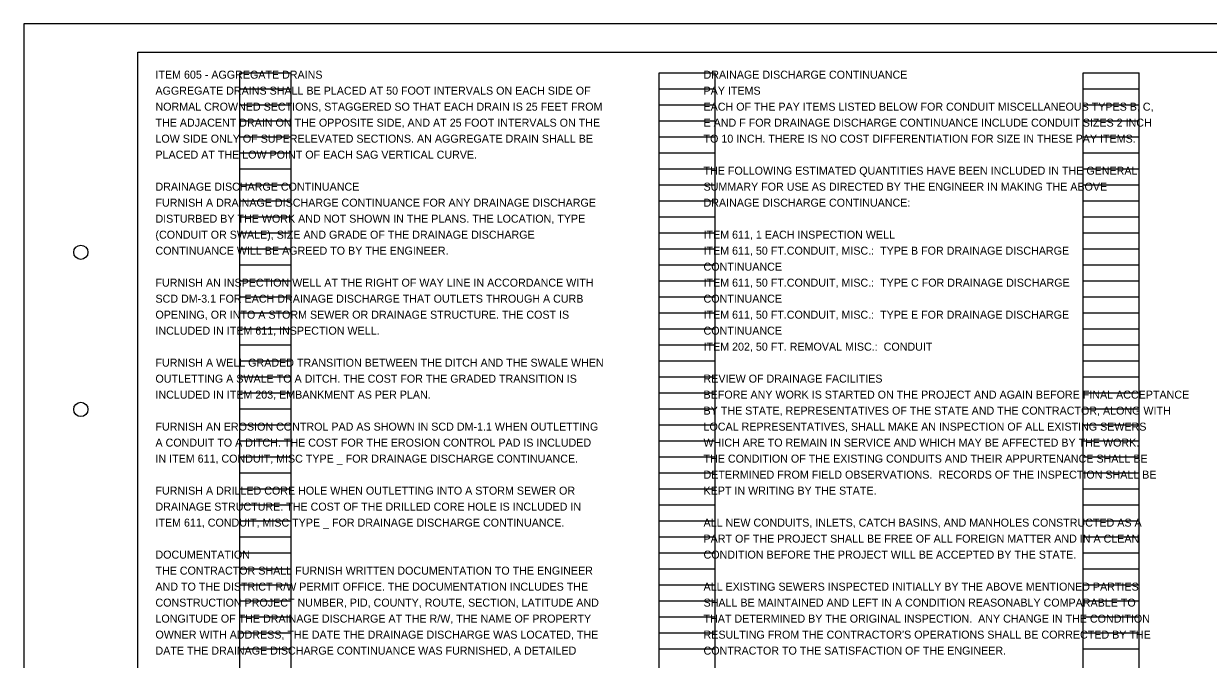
# Model space of a CAD drawing. Extents: x -16 to 102, y -13 to 9.
# Drawn here: x 27.86 to 48.59, y -2.03 to 9.09 of the extents above; entities that cross this region are included whole.
import ezdxf

# ---------------------------------------------------------------- set-up
doc = ezdxf.new("R2010")
doc.units = 0
for name, color, linetype in [('SH_Border', 7, 'Continuous'), ('SH_Cut_Line', 7, 'Continuous'), ('SH_Data', 7, 'Continuous'), ('TX_P_1', 7, 'Continuous')]:
    doc.layers.add(name, color=color, linetype=linetype)

msp = doc.modelspace()

# ---------------------------------------------------------------- linework, layer by layer
at = {"layer": 'SH_Border'}
msp.add_lwpolyline([(29.861, 8.593), (61.361, 8.593), (61.361, -12.407), (29.861, -12.407)], close=True, dxfattribs=at)
for centre in [(28.861, 5.093), (28.861, 2.343)]:
    msp.add_circle(centre, 0.125, dxfattribs=at)
at = {"layer": 'SH_Cut_Line'}
msp.add_lwpolyline([(27.861, -12.907), (61.861, -12.907), (61.861, 9.093), (27.861, 9.093)], close=True, dxfattribs=at)
at = {"layer": 'SH_Data'}
for p, q in [((31.642, -11.927), (31.642, 8.233)), ((31.642, 8.233), (32.542, 8.233)), ((32.542, -11.927), (32.542, 8.233)), ((38.982, -11.927), (38.982, 8.233)), ((38.982, 8.233), (39.962, 8.233)), ((39.962, -11.927), (39.962, 8.233)), ((46.402, -11.927), (46.402, 8.233)), ((46.402, 8.233), (47.382, 8.233)), ((47.382, -11.927), (47.382, 8.233)), ((31.642, 7.953), (32.542, 7.953)), ((38.982, 7.953), (39.962, 7.953)), ((46.402, 7.953), (47.382, 7.953)), ((31.642, 7.673), (32.542, 7.673)), ((38.982, 7.673), (39.962, 7.673)), ((46.402, 7.673), (47.382, 7.673)), ((31.642, 7.393), (32.542, 7.393)), ((38.982, 7.393), (39.962, 7.393)), ((46.402, 7.393), (47.382, 7.393)), ((31.642, 7.113), (32.542, 7.113)), ((38.982, 7.113), (39.962, 7.113)), ((46.402, 7.113), (47.382, 7.113)), ((31.642, 6.833), (32.542, 6.833)), ((38.982, 6.833), (39.962, 6.833)), ((46.402, 6.833), (47.382, 6.833)), ((31.642, 6.553), (32.542, 6.553)), ((38.982, 6.553), (39.962, 6.553)), ((46.402, 6.553), (47.382, 6.553)), ((31.642, 6.273), (32.542, 6.273)), ((38.982, 6.273), (39.962, 6.273)), ((46.402, 6.273), (47.382, 6.273)), ((31.642, 5.993), (32.542, 5.993)), ((38.982, 5.993), (39.962, 5.993)), ((46.402, 5.993), (47.382, 5.993)), ((31.642, 5.713), (32.542, 5.713)), ((38.982, 5.713), (39.962, 5.713)), ((46.402, 5.713), (47.382, 5.713)), ((31.642, 5.433), (32.542, 5.433)), ((38.982, 5.433), (39.962, 5.433)), ((46.402, 5.433), (47.382, 5.433)), ((31.642, 5.153), (32.542, 5.153)), ((38.982, 5.153), (39.962, 5.153)), ((46.402, 5.153), (47.382, 5.153)), ((31.642, 4.873), (32.542, 4.873)), ((38.982, 4.873), (39.962, 4.873)), ((46.402, 4.873), (47.382, 4.873)), ((31.642, 4.593), (32.542, 4.593)), ((38.982, 4.593), (39.962, 4.593)), ((46.402, 4.593), (47.382, 4.593)), ((31.642, 4.313), (32.542, 4.313)), ((38.982, 4.313), (39.962, 4.313)), ((46.402, 4.313), (47.382, 4.313)), ((31.642, 4.033), (32.542, 4.033)), ((38.982, 4.033), (39.962, 4.033)), ((46.402, 4.033), (47.382, 4.033)), ((31.642, 3.753), (32.542, 3.753)), ((38.982, 3.753), (39.962, 3.753)), ((46.402, 3.753), (47.382, 3.753)), ((31.642, 3.473), (32.542, 3.473)), ((38.982, 3.473), (39.962, 3.473)), ((46.402, 3.473), (47.382, 3.473)), ((31.642, 3.193), (32.542, 3.193)), ((38.982, 3.193), (39.962, 3.193)), ((46.402, 3.193), (47.382, 3.193)), ((31.642, 2.913), (32.542, 2.913)), ((38.982, 2.913), (39.962, 2.913)), ((46.402, 2.913), (47.382, 2.913)), ((31.642, 2.633), (32.542, 2.633)), ((38.982, 2.633), (39.962, 2.633)), ((46.402, 2.633), (47.382, 2.633)), ((31.642, 2.353), (32.542, 2.353)), ((38.982, 2.353), (39.962, 2.353)), ((46.402, 2.353), (47.382, 2.353)), ((31.642, 2.073), (32.542, 2.073)), ((38.982, 2.073), (39.962, 2.073)), ((46.402, 2.073), (47.382, 2.073)), ((31.642, 1.793), (32.542, 1.793)), ((38.982, 1.793), (39.962, 1.793)), ((46.402, 1.793), (47.382, 1.793)), ((31.642, 1.513), (32.542, 1.513)), ((38.982, 1.513), (39.962, 1.513)), ((46.402, 1.513), (47.382, 1.513)), ((31.642, 1.233), (32.542, 1.233)), ((38.982, 1.233), (39.962, 1.233)), ((46.402, 1.233), (47.382, 1.233)), ((31.642, 0.953), (32.542, 0.953)), ((38.982, 0.953), (39.962, 0.953)), ((46.402, 0.953), (47.382, 0.953)), ((31.642, 0.673), (32.542, 0.673)), ((38.982, 0.673), (39.962, 0.673)), ((46.402, 0.673), (47.382, 0.673)), ((31.642, 0.393), (32.542, 0.393)), ((38.982, 0.393), (39.962, 0.393)), ((46.402, 0.393), (47.382, 0.393)), ((31.642, 0.113), (32.542, 0.113)), ((38.982, 0.113), (39.962, 0.113)), ((46.402, 0.113), (47.382, 0.113)), ((31.642, -0.167), (32.542, -0.167)), ((38.982, -0.167), (39.962, -0.167)), ((46.402, -0.167), (47.382, -0.167)), ((31.642, -0.447), (32.542, -0.447)), ((38.982, -0.447), (39.962, -0.447)), ((46.402, -0.447), (47.382, -0.447)), ((31.642, -0.727), (32.542, -0.727)), ((38.982, -0.727), (39.962, -0.727)), ((46.402, -0.727), (47.382, -0.727)), ((31.642, -1.007), (32.542, -1.007)), ((38.982, -1.007), (39.962, -1.007)), ((46.402, -1.007), (47.382, -1.007)), ((31.642, -1.287), (32.542, -1.287)), ((38.982, -1.287), (39.962, -1.287)), ((46.402, -1.287), (47.382, -1.287)), ((31.642, -1.567), (32.542, -1.567)), ((38.982, -1.567), (39.962, -1.567)), ((46.402, -1.567), (47.382, -1.567)), ((31.642, -1.847), (32.542, -1.847)), ((38.982, -1.847), (39.962, -1.847)), ((46.402, -1.847), (47.382, -1.847))]:
    msp.add_line(p, q, dxfattribs=at)

# ---------------------------------------------------------------- texts
at = {"layer": 'TX_P_1'}
for s, p in [('ITEM 605 - AGGREGATE DRAINS', (30.167, 8.131)), ('DRAINAGE DISCHARGE CONTINUANCE', (39.758, 8.131)), ('AGGREGATE DRAINS SHALL BE PLACED AT 50 FOOT INTERVALS ON EACH SIDE OF', (30.167, 7.851)), ('PAY ITEMS', (39.758, 7.851)), ('NORMAL CROWNED SECTIONS, STAGGERED SO THAT EACH DRAIN IS 25 FEET FROM', (30.167, 7.571)), ('EACH OF THE PAY ITEMS LISTED BELOW FOR CONDUIT MISCELLANEOUS TYPES B, C,', (39.758, 7.571)), ('THE ADJACENT DRAIN ON THE OPPOSITE SIDE, AND AT 25 FOOT INTERVALS ON THE', (30.167, 7.291)), ('E AND F FOR DRAINAGE DISCHARGE CONTINUANCE INCLUDE CONDUIT SIZES 2 INCH', (39.758, 7.291)), ('LOW SIDE ONLY OF SUPERELEVATED SECTIONS. AN AGGREGATE DRAIN SHALL BE', (30.167, 7.011)), ('TO 10 INCH. THERE IS NO COST DIFFERENTIATION FOR SIZE IN THESE PAY ITEMS.', (39.758, 7.011)), ('PLACED AT THE LOW POINT OF EACH SAG VERTICAL CURVE.', (30.167, 6.731)), ('THE FOLLOWING ESTIMATED QUANTITIES HAVE BEEN INCLUDED IN THE GENERAL', (39.758, 6.451)), ('DRAINAGE DISCHARGE CONTINUANCE', (30.167, 6.171)), ('SUMMARY FOR USE AS DIRECTED BY THE ENGINEER IN MAKING THE ABOVE', (39.758, 6.171)), ('FURNISH A DRAINAGE DISCHARGE CONTINUANCE FOR ANY DRAINAGE DISCHARGE', (30.167, 5.891)), ('DRAINAGE DISCHARGE CONTINUANCE:', (39.758, 5.891)), ('DISTURBED BY THE WORK AND NOT SHOWN IN THE PLANS. THE LOCATION, TYPE', (30.167, 5.611)), ('(CONDUIT OR SWALE), SIZE AND GRADE OF THE DRAINAGE DISCHARGE', (30.167, 5.331)), ('ITEM 611, 1 EACH INSPECTION WELL', (39.758, 5.331)), ('CONTINUANCE WILL BE AGREED TO BY THE ENGINEER.', (30.167, 5.051)), ('ITEM 611, 50 FT.CONDUIT, MISC.:  TYPE B FOR DRAINAGE DISCHARGE', (39.758, 5.051)), ('CONTINUANCE ', (39.758, 4.771)), ('FURNISH AN INSPECTION WELL AT THE RIGHT OF WAY LINE IN ACCORDANCE WITH', (30.167, 4.491)), ('ITEM 611, 50 FT.CONDUIT, MISC.:  TYPE C FOR DRAINAGE DISCHARGE', (39.758, 4.491)), ('SCD DM-3.1 FOR EACH DRAINAGE DISCHARGE THAT OUTLETS THROUGH A CURB', (30.167, 4.211)), ('CONTINUANCE', (39.758, 4.211)), ('OPENING, OR INTO A STORM SEWER OR DRAINAGE STRUCTURE. THE COST IS', (30.167, 3.931)), ('ITEM 611, 50 FT.CONDUIT, MISC.:  TYPE E FOR DRAINAGE DISCHARGE', (39.758, 3.931)), ('INCLUDED IN ITEM 611, INSPECTION WELL.', (30.167, 3.651)), ('CONTINUANCE', (39.758, 3.651)), ('ITEM 202, 50 FT. REMOVAL MISC.:  CONDUIT', (39.758, 3.371)), ('FURNISH A WELL GRADED TRANSITION BETWEEN THE DITCH AND THE SWALE WHEN', (30.167, 3.091)), ('OUTLETTING A SWALE TO A DITCH. THE COST FOR THE GRADED TRANSITION IS', (30.167, 2.811)), ('REVIEW OF DRAINAGE FACILITIES', (39.758, 2.812)), ('INCLUDED IN ITEM 203, EMBANKMENT AS PER PLAN.', (30.167, 2.532)), ('BEFORE ANY WORK IS STARTED ON THE PROJECT AND AGAIN BEFORE FINAL ACCEPTANCE', (39.758, 2.532)), ('BY THE STATE, REPRESENTATIVES OF THE STATE AND THE CONTRACTOR, ALONG WITH', (39.758, 2.252)), ('FURNISH AN EROSION CONTROL PAD AS SHOWN IN SCD DM-1.1 WHEN OUTLETTING', (30.167, 1.972)), ('LOCAL REPRESENTATIVES, SHALL MAKE AN INSPECTION OF ALL EXISTING SEWERS', (39.758, 1.972)), ('A CONDUIT TO A DITCH. THE COST FOR THE EROSION CONTROL PAD IS INCLUDED', (30.167, 1.692)), ('WHICH ARE TO REMAIN IN SERVICE AND WHICH MAY BE AFFECTED BY THE WORK.', (39.758, 1.692)), ('IN ITEM 611, CONDUIT, MISC TYPE _ FOR DRAINAGE DISCHARGE CONTINUANCE.', (30.167, 1.412)), ('THE CONDITION OF THE EXISTING CONDUITS AND THEIR APPURTENANCE SHALL BE ', (39.758, 1.412)), ('DETERMINED FROM FIELD OBSERVATIONS.  RECORDS OF THE INSPECTION SHALL BE', (39.758, 1.132)), ('FURNISH A DRILLED CORE HOLE WHEN OUTLETTING INTO A STORM SEWER OR', (30.167, 0.852)), ('KEPT IN WRITING BY THE STATE.', (39.758, 0.852)), ('DRAINAGE STRUCTURE. THE COST OF THE DRILLED CORE HOLE IS INCLUDED IN', (30.167, 0.572)), ('ITEM 611, CONDUIT, MISC TYPE _ FOR DRAINAGE DISCHARGE CONTINUANCE. ', (30.167, 0.292)), ('ALL NEW CONDUITS, INLETS, CATCH BASINS, AND MANHOLES CONSTRUCTED AS A', (39.758, 0.292)), ('PART OF THE PROJECT SHALL BE FREE OF ALL FOREIGN MATTER AND IN A CLEAN', (39.758, 0.012)), ('DOCUMENTATION', (30.167, -0.268)), ('CONDITION BEFORE THE PROJECT WILL BE ACCEPTED BY THE STATE.', (39.758, -0.268)), ('THE CONTRACTOR SHALL FURNISH WRITTEN DOCUMENTATION TO THE ENGINEER', (30.167, -0.548)), ('AND TO THE DISTRICT R/W PERMIT OFFICE. THE DOCUMENTATION INCLUDES THE', (30.167, -0.828)), ('ALL EXISTING SEWERS INSPECTED INITIALLY BY THE ABOVE MENTIONED PARTIES', (39.758, -0.828)), ('CONSTRUCTION PROJECT NUMBER, PID, COUNTY, ROUTE, SECTION, LATITUDE AND', (30.167, -1.108)), ('SHALL BE MAINTAINED AND LEFT IN A CONDITION REASONABLY COMPARABLE TO', (39.758, -1.108)), ('LONGITUDE OF THE DRAINAGE DISCHARGE AT THE R/W, THE NAME OF PROPERTY', (30.167, -1.388)), ('THAT DETERMINED BY THE ORIGINAL INSPECTION.  ANY CHANGE IN THE CONDITION', (39.758, -1.388)), ('OWNER WITH ADDRESS, THE DATE THE DRAINAGE DISCHARGE WAS LOCATED, THE', (30.167, -1.668)), ("RESULTING FROM THE CONTRACTOR'S OPERATIONS SHALL BE CORRECTED BY THE", (39.758, -1.668)), ('DATE THE DRAINAGE DISCHARGE CONTINUANCE WAS FURNISHED, A DETAILED', (30.167, -1.948)), ('CONTRACTOR TO THE SATISFACTION OF THE ENGINEER.', (39.758, -1.948))]:
    msp.add_text(s, height=0.14, dxfattribs=at).set_placement(p)

doc.saveas('drawing.dxf')
